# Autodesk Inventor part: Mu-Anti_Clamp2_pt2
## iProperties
Shininess: 64.0
Length Units: 11272
Angle Units: 11279
Time Units: 11290
Mass Units: 11286
Length Display Precision: 3
Angle Display Precision: 2
Compacted: True
Part Number: Mu-Anti_Clamp2_pt2
Document SubType Name: Modeling
Created: 2004-08
Designer: John Blackburn
Material: Aluminum-6061
Manufacturer: Standard
Standards Organization: Custom
Density: 0.0
Volumn: 0.0
Area: 0.0
PropertySet Name: Model Information
Control State: 0
Master: False
Checked Out: False
Author: John Blackburn
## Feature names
1. Extrusion1
2. Split1
